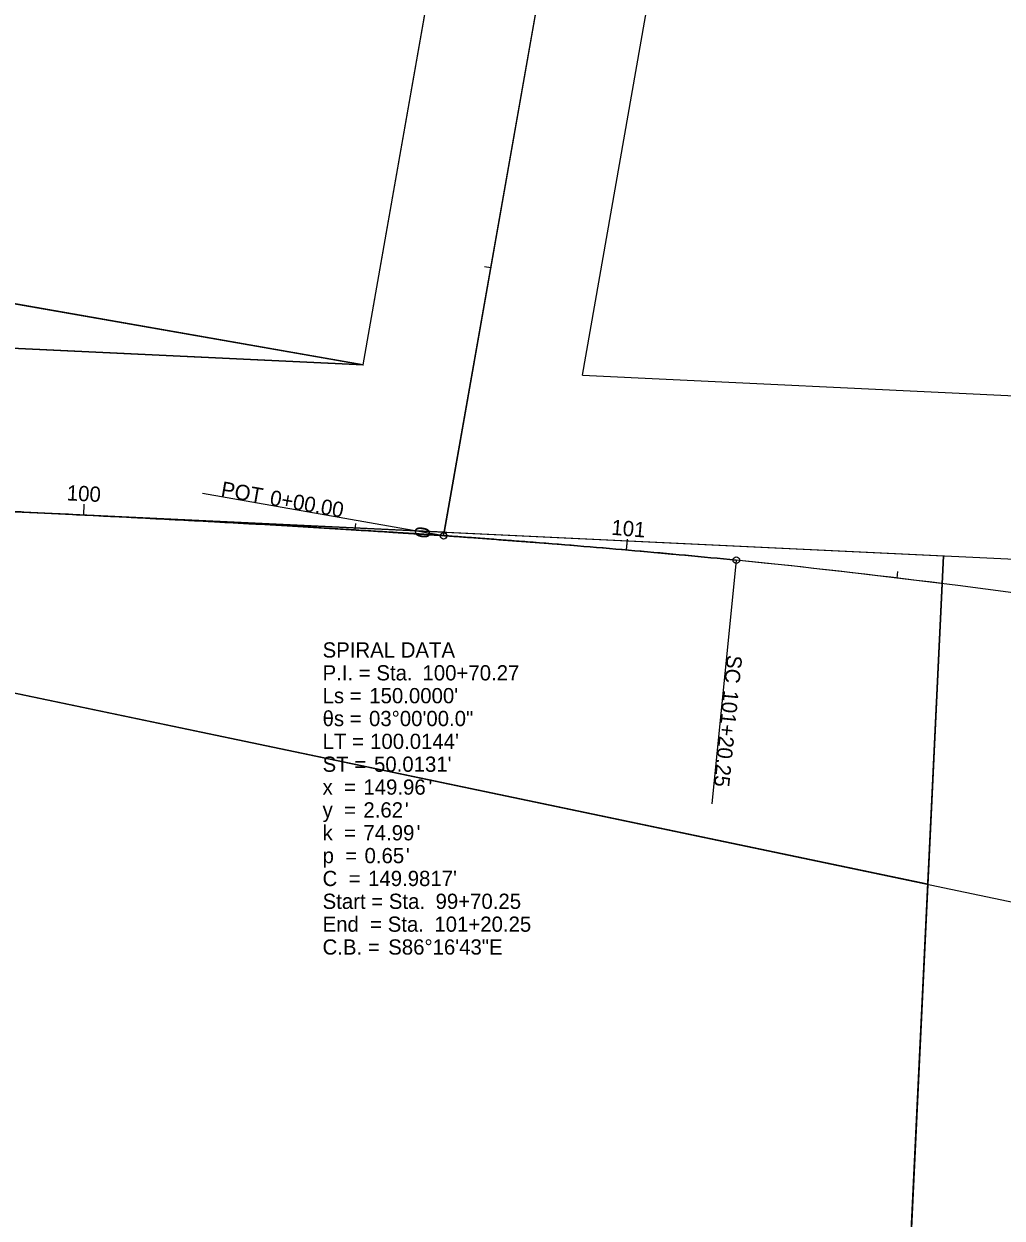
# Model space of a CAD drawing. Extents: x 2318731 to 2320621, y 732958 to 734198.
# Drawn here: x 2319324.8 to 2319504.6, y 733409.1 to 733628.7 of the extents above; entities that cross this region are included whole.
import ezdxf

# ---------------------------------------------------------------- set-up
doc = ezdxf.new("R2010")
doc.units = 0
for name, color, linetype in [('RW_P_Easement_Area', 7, 'Continuous'), ('RW_P_Esmt_TMP', 7, 'Continuous'), ('RW_X_CL_100_Cardinal_Points', 7, 'Continuous'), ('RW_X_CL_100_Stations', 7, 'Continuous'), ('RW_X_CL_500_Cardinal_Points', 7, 'Continuous'), ('RW_X_CL_500_Curve_Data', 7, 'Continuous'), ('RW_X_CL_500_Stations', 7, 'Continuous'), ('SC_Scratch3', 7, 'Continuous'), ('SC_Scratch4', 7, 'Continuous'), ('SC_Scratch5', 7, 'Continuous'), ('SV_P_Control_Cells_Set', 7, 'Continuous'), ('V-SURV-IPF', 7, 'Continuous'), ('V-SURV-PARL-LINE', 7, 'Continuous'), ('V-SURV-PARL-SUBL', 7, 'Continuous'), ('V-SURV-RWAY', 7, 'Continuous')]:
    doc.layers.add(name, color=color, linetype=linetype)

msp = doc.modelspace()

# ---------------------------------------------------------------- linework, layer by layer
at = {"layer": 'RW_P_Easement_Area'}
for p, q in [((2319317.64, 733578.16), (2319387.15, 733565.99)), ((2319387.15, 733565.99), (2319317.22, 733569.31))]:
    msp.add_line(p, q, dxfattribs=at)
at = {"layer": 'RW_P_Esmt_TMP'}
msp.add_line((2319317.64, 733578.16), (2319387.15, 733565.99), dxfattribs=at)
at = {"layer": 'RW_X_CL_100_Cardinal_Points'}
for p, q in [((2319401.93, 733534.57), (2319357.61, 733542.36)), ((2319455.72, 733530.08), (2319451.23, 733485.3))]:
    msp.add_line(p, q, dxfattribs=at)
for centre in [(2319401.93, 733534.57), (2319455.72, 733530.08)]:
    msp.add_circle(centre, 0.6, dxfattribs=at)
at = {"layer": 'RW_X_CL_100_Stations'}
for p, q in [((2319410.59, 733583.81), (2319409.41, 733584.02)), ((2319335.77, 733538.38), (2319335.86, 733540.38)), ((2319385.69, 733535.63), (2319385.76, 733536.83)), ((2319401.93, 733534.57), (2319399.96, 733534.91)), ((2319435.55, 733531.96), (2319435.73, 733533.95)), ((2319485.28, 733526.8), (2319485.43, 733527.99))]:
    msp.add_line(p, q, dxfattribs=at)
at = {"layer": 'RW_X_CL_500_Cardinal_Points'}
for p, q in [((2319401.93, 733534.57), (2319357.61, 733542.36)), ((2319455.72, 733530.08), (2319451.23, 733485.3))]:
    msp.add_line(p, q, dxfattribs=at)
for centre in [(2319401.93, 733534.57), (2319455.72, 733530.08)]:
    msp.add_circle(centre, 0.6, dxfattribs=at)
at = {"layer": 'RW_X_CL_500_Stations'}
for p, q in [((2319335.77, 733538.38), (2319335.86, 733540.38)), ((2319401.93, 733534.57), (2319399.96, 733534.91)), ((2319435.55, 733531.96), (2319435.66, 733533.15))]:
    msp.add_line(p, q, dxfattribs=at)
at = {"layer": 'SC_Scratch3'}
msp.add_lwpolyline([(2319228.62, 733583.02), (2319227.77, 733574.05), (2319233.75, 733573.49), (2319234.34, 733579.7), (2319317.45, 733574.31), (2319317.21, 733569.31), (2319387.15, 733565.99), (2319317.63, 733578.16)], close=True, dxfattribs=at)
at = {"layer": 'SC_Scratch4'}
for points in [[(2319238.01, 733573.08), (2319387.15, 733565.99), (2319438.37, 733857.2), (2319458.71, 733857.41), (2319402.05, 733535.25), (2319235.88, 733543.15), (2319201.73, 733546.4), (2319204.58, 733576.26)], [(2319303.98, 733539.91), (2319493.77, 733530.89), (2319490.9, 733470.51), (2319302.56, 733509.94)]]:
    msp.add_lwpolyline(points, close=True, dxfattribs=at)
at = {"layer": 'SC_Scratch5'}
msp.add_lwpolyline([(2319402.05, 733535.25), (2319235.88, 733543.15), (2319201.73, 733546.4), (2319231.12, 733855.03), (2319458.71, 733857.41)], close=True, dxfattribs=at)
for points in [[(2319493.53, 733525.78), (2319478.1, 733201.26), (2319288.31, 733210.28), (2319303.98, 733539.91), (2319306.05, 733539.81)], [(2319306.05, 733539.81), (2319493.77, 733530.89), (2319493.53, 733525.78)]]:
    msp.add_lwpolyline(points, dxfattribs=at)
msp.add_arc((2319312.92, 732104.82), 1432.39, 82.75649, 84.27847, dxfattribs=at)
msp.add_arc((2319312.92, 732104.82), 1432.39, 82.75649, 84.27847, dxfattribs=at)
for points, degree in [([(2319324.78, 733538.92), (2319318.54, 733539.22), (2319312.3, 733539.51), (2319306.05, 733539.81)], 2), ([(2319324.78, 733538.92), (2319331.03, 733538.61), (2319349.75, 733537.69), (2319368.48, 733536.68), (2319380.95, 733535.92)], 3), ([(2319380.95, 733535.92), (2319368.48, 733536.68), (2319349.75, 733537.69), (2319331.03, 733538.61), (2319324.78, 733538.92)], 3), ([(2319380.95, 733535.92), (2319393.43, 733535.17), (2319405.9, 733534.33), (2319418.37, 733533.37)], 2), ([(2319418.37, 733533.37), (2319405.9, 733534.33), (2319393.43, 733535.17), (2319380.95, 733535.92)], 2), ([(2319418.37, 733533.37), (2319424.6, 733532.89), (2319437.06, 733531.86), (2319449.5, 733530.7), (2319455.72, 733530.08)], 3), ([(2319455.72, 733530.08), (2319449.5, 733530.7), (2319437.06, 733531.86), (2319424.6, 733532.89), (2319418.37, 733533.37)], 3)]:
    msp.add_open_spline(points, degree=degree, dxfattribs=at)
at = {"layer": 'SV_P_Control_Cells_Set'}
for p, q in [((2319387.1, 733565.99), (2319387.19, 733565.99)), ((2319387.14, 733565.94), (2319387.15, 733566.04))]:
    msp.add_line(p, q, dxfattribs=at)
at = {"layer": 'V-SURV-IPF'}
for p, q in [((2319306.05, 733539.81), (2319793.43, 733516.64)), ((2319478.1, 733201.26), (2319493.77, 733530.89))]:
    msp.add_line(p, q, dxfattribs=at)
at = {"layer": 'V-SURV-PARL-LINE'}
for p, q in [((2319387.15, 733565.99), (2319476.73, 734075.32)), ((2319427.43, 733564.08), (2319479.14, 733858.08)), ((2319238.01, 733573.08), (2319387.15, 733565.99)), ((2319427.43, 733564.08), (2319803.49, 733546.2)), ((2319302.56, 733509.94), (2319715.9, 733423.39))]:
    msp.add_line(p, q, dxfattribs=at)
at = {"layer": 'V-SURV-RWAY'}
msp.add_line((2319401.93, 733534.57), (2319478.69, 733971.04), dxfattribs=at)
msp.add_arc((2319312.92, 732104.82), 1432.39, 58.12986, 84.27847, dxfattribs=at)
msp.add_open_spline([(2319306.05, 733539.81), (2319312.3, 733539.51), (2319324.78, 733538.92), (2319349.75, 733537.69), (2319380.96, 733536), (2319412.14, 733533.91), (2319437.06, 733531.86), (2319449.5, 733530.7), (2319455.72, 733530.08)], degree=3, dxfattribs=at)

# ---------------------------------------------------------------- texts
at = {"layer": 'RW_X_CL_100_Cardinal_Points'}
for s, rotation, p in [('POT', 350.0249, (2319360.86, 733541.84)), ('0+00.00', 350.0249, (2319369.85, 733540.25)), ('SC', 264.2785, (2319454.03, 733512.75)), ('101+20.25', 264.2785, (2319453.38, 733506.26))]:
    msp.add_text(s, height=2.8, rotation=rotation, dxfattribs=at).set_placement(p)
at = {"layer": 'RW_X_CL_100_Stations'}
for s, rotation, p in [('100', 357.1605, (2319332.62, 733541.08)), ('101', 355.034, (2319432.67, 733534.77)), ('0', 80.0249, (2319399.23, 733533.92))]:
    msp.add_text(s, height=2.8, rotation=rotation, dxfattribs=at).set_placement(p)
at = {"layer": 'RW_X_CL_500_Cardinal_Points'}
for s, rotation, p in [('POT', 350.0249, (2319360.86, 733541.84)), ('0+00.00', 350.0249, (2319369.85, 733540.25)), ('SC', 264.2785, (2319454.03, 733512.75)), ('101+20.25', 264.2785, (2319453.38, 733506.26))]:
    msp.add_text(s, height=2.8, rotation=rotation, dxfattribs=at).set_placement(p)
at = {"layer": 'RW_X_CL_500_Curve_Data'}
for s, p in [('SPIRAL DATA', (2319379.68, 733512.18)), ('P.I. = Sta. ', (2319379.68, 733507.98)), ('100+70.27', (2319398.04, 733507.98)), ('Ls = ', (2319379.68, 733503.78)), ("150.0000'", (2319388.26, 733503.78)), ('θs = ', (2319379.68, 733499.58)), ('03°00\'00.0"', (2319388.21, 733499.58)), ('LT = ', (2319379.68, 733495.38)), ("100.0144'", (2319388.41, 733495.38)), ('ST = ', (2319379.68, 733491.18)), ("50.0131'", (2319389.13, 733491.18)), ('x  = ', (2319379.68, 733486.98)), ('149.96', (2319387.18, 733486.98)), ("'", (2319399.14, 733486.98)), ('y  = ', (2319379.68, 733482.78)), ('2.62', (2319387.18, 733482.78)), ("'", (2319394.79, 733482.78)), ('k  = ', (2319379.68, 733478.58)), ('74.99', (2319387.18, 733478.58)), ("'", (2319396.96, 733478.58)), ('p  = ', (2319379.68, 733474.38)), ('0.65', (2319387.39, 733474.38)), ("'", (2319395, 733474.38)), ('C  = ', (2319379.68, 733470.18)), ("149.9817'", (2319388.04, 733470.18)), ('Start = Sta. ', (2319379.68, 733465.98)), ('99+70.25', (2319400.44, 733465.98)), ('End  = Sta. ', (2319379.68, 733461.78)), ('101+20.25', (2319400.22, 733461.78)), ('C.B. = ', (2319379.68, 733457.58)), ('S86°16\'43"E', (2319391.74, 733457.58))]:
    msp.add_text(s, height=2.8, dxfattribs=at).set_placement(p)
at = {"layer": 'RW_X_CL_500_Stations'}
for s, rotation, p in [('100', 357.1605, (2319332.62, 733541.08)), ('0', 80.0249, (2319399.23, 733533.92))]:
    msp.add_text(s, height=2.8, rotation=rotation, dxfattribs=at).set_placement(p)
at = {"layer": 'V-SURV-PARL-SUBL'}
for s, p in [('SPIRAL DATA', (2319379.68, 733512.18)), ('P.I. = Sta. ', (2319379.68, 733507.98)), ('100+70.27', (2319398.04, 733507.98)), ('Ls = ', (2319379.68, 733503.78)), ("150.0000'", (2319388.26, 733503.78)), ('θs = ', (2319379.68, 733499.58)), ('03°00\'00.0"', (2319388.21, 733499.58)), ('LT = ', (2319379.68, 733495.38)), ("100.0144'", (2319388.41, 733495.38)), ('ST = ', (2319379.68, 733491.18)), ("50.0131'", (2319389.13, 733491.18)), ('x  = ', (2319379.68, 733486.98)), ('149.96', (2319387.18, 733486.98)), ("'", (2319399.14, 733486.98)), ('y  = ', (2319379.68, 733482.78)), ('2.62', (2319387.18, 733482.78)), ("'", (2319394.79, 733482.78)), ('k  = ', (2319379.68, 733478.58)), ('74.99', (2319387.18, 733478.58)), ("'", (2319396.96, 733478.58)), ('p  = ', (2319379.68, 733474.38)), ('0.65', (2319387.39, 733474.38)), ("'", (2319395, 733474.38)), ('C  = ', (2319379.68, 733470.18)), ("149.9817'", (2319388.04, 733470.18)), ('Start = Sta. ', (2319379.68, 733465.98)), ('99+70.25', (2319400.44, 733465.98)), ('End  = Sta. ', (2319379.68, 733461.78)), ('101+20.25', (2319400.22, 733461.78)), ('C.B. = ', (2319379.68, 733457.58)), ('S86°16\'43"E', (2319391.74, 733457.58))]:
    msp.add_text(s, height=2.8, dxfattribs=at).set_placement(p)

doc.saveas('drawing.dxf')
